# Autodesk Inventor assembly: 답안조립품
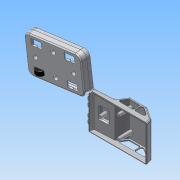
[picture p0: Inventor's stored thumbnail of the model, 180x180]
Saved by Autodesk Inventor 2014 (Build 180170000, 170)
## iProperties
Created: 2015-05
Part Number: 답안조립품
Document SubType Name: Assembly
Designer: Administrator
Author: Administrator
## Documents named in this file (5)
- C:\Documents and Settings\Administrator\바탕 화면\450507V1013\답안조립품.iam
- C:\Documents and Settings\Administrator\바탕 화면\450507V1013\1-본체.ipt
- C:\Documents and Settings\Administrator\바탕 화면\450507V1013\커버.ipt
- C:\Documents and Settings\Administrator\바탕 화면\450507V1013\바퀴.ipt
- C:\Documents and Settings\Administrator\바탕 화면\450507V1013\바퀴고정부.ipt
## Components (1 placed, 1 different names)
1. 1-본체:1
